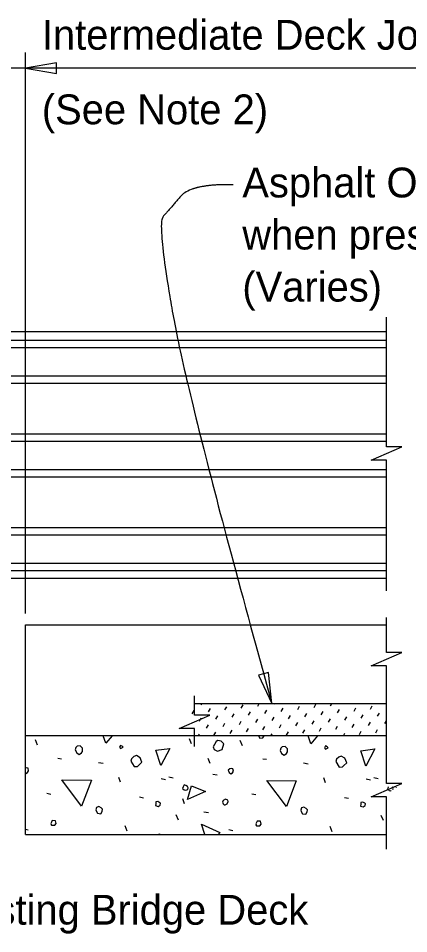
# Model space of a CAD drawing. Extents: x 21629.5 to 21698.8, y 56199.1 to 56237.6.
# Drawn here: x 21643.08 to 21645.71, y 56213.42 to 56219.6 of the extents above; entities that cross this region are included whole.
import ezdxf

# ---------------------------------------------------------------- set-up
doc = ezdxf.new("R2010")
doc.units = 0
for name, color, linetype in [('Dimension', 7, 'Continuous'), ('ExistSuperStruct', 7, 'Continuous'), ('Miscellaneous', 7, 'Continuous'), ('SteelMisc', 7, 'Continuous'), ('TextStructures', 7, 'Continuous')]:
    doc.layers.add(name, color=color, linetype=linetype)

msp = doc.modelspace()

# ---------------------------------------------------------------- linework, layer by layer
at = {"layer": 'Dimension'}
for p, q in [((21643.1252, 56215.5808), (21643.1252, 56219.372)), ((21647.048, 56219.267), (21641.4764, 56219.267))]:
    msp.add_line(p, q, dxfattribs=at)
for points in [[(21643.1251, 56219.267), (21643.3334, 56219.2318), (21643.3334, 56219.3023)], [(21644.7886, 56214.9723), (21644.7671, 56215.1824), (21644.6991, 56215.1636)]]:
    msp.add_lwpolyline(points, close=True, dxfattribs=at)
for points in [[(21645.5635, 56215.734), (21645.5635, 56216.6173), (21645.4601, 56216.6173), (21645.5635, 56216.6623), (21645.6668, 56216.7073), (21645.5635, 56216.7073), (21645.5635, 56217.5837)], [(21645.5635, 56214.7572), (21645.5635, 56215.2273), (21645.4601, 56215.2273), (21645.5635, 56215.2723), (21645.6668, 56215.3173), (21645.5635, 56215.3173), (21645.5635, 56215.5547)], [(21644.2668, 56214.6826), (21644.2668, 56214.8034), (21644.1635, 56214.8034), (21644.2668, 56214.8484), (21644.3701, 56214.8934), (21644.2668, 56214.8934), (21644.2668, 56215.024)], [(21645.5635, 56213.9879), (21645.5635, 56214.3427), (21645.4601, 56214.3427), (21645.5635, 56214.3877), (21645.6668, 56214.4327), (21645.5635, 56214.4327), (21645.5635, 56214.7572)]]:
    msp.add_lwpolyline(points, dxfattribs=at)
msp.add_open_spline([(21644.5276, 56218.4788), (21644.2443, 56218.4855), (21644.0959, 56218.3098), (21644.0132, 56218.2199), (21644.2161, 56217.0441), (21644.7886, 56214.9723)], degree=2, dxfattribs=at)
at = {"layer": 'ExistSuperStruct'}
for p, q in [((21643.1252, 56214.0879), (21643.1252, 56215.5045)), ((21643.1252, 56215.5045), (21645.5634, 56215.5045)), ((21644.2668, 56214.9734), (21645.5634, 56214.9734)), ((21645.5634, 56214.7545), (21643.1252, 56214.7545)), ((21643.1252, 56214.0879), (21645.5634, 56214.0879))]:
    msp.add_line(p, q, dxfattribs=at)
at = {"layer": 'Miscellaneous'}
for p, q in [((21644.2508, 56214.903), (21644.2638, 56214.9254)), ((21644.3126, 56214.9648), (21644.3176, 56214.9734)), ((21644.3615, 56214.916), (21644.3744, 56214.9384)), ((21644.4721, 56214.929), (21644.4851, 56214.9513)), ((21644.5827, 56214.9419), (21644.5957, 56214.9643)), ((21644.6316, 56214.8931), (21644.6445, 56214.9155)), ((21644.6934, 56214.9549), (21644.7041, 56214.9734)), ((21644.7422, 56214.906), (21644.7552, 56214.9284)), ((21644.804, 56214.9678), (21644.8072, 56214.9734)), ((21644.8528, 56214.919), (21644.8658, 56214.9414)), ((21644.9635, 56214.932), (21644.9764, 56214.9544)), ((21645.0741, 56214.9449), (21645.0871, 56214.9673)), ((21645.1229, 56214.8961), (21645.1359, 56214.9185)), ((21645.1847, 56214.9579), (21645.1937, 56214.9734)), ((21645.2336, 56214.9091), (21645.2465, 56214.9315)), ((21645.2954, 56214.9709), (21645.2969, 56214.9734)), ((21645.3442, 56214.922), (21645.3572, 56214.9444)), ((21645.4548, 56214.935), (21645.4678, 56214.9574)), ((21644.2997, 56214.8542), (21644.3126, 56214.8766)), ((21644.4103, 56214.8672), (21644.4233, 56214.8895)), ((21644.5209, 56214.8801), (21644.5339, 56214.9025)), ((21644.5698, 56214.8313), (21644.5827, 56214.8537)), ((21644.6804, 56214.8442), (21644.6934, 56214.8666)), ((21644.791, 56214.8572), (21644.804, 56214.8796)), ((21644.9017, 56214.8702), (21644.9146, 56214.8926)), ((21645.0123, 56214.8831), (21645.0253, 56214.9055)), ((21645.0611, 56214.8343), (21645.0741, 56214.8567)), ((21645.1718, 56214.8473), (21645.1847, 56214.8697)), ((21645.2824, 56214.8602), (21645.2954, 56214.8826)), ((21645.393, 56214.8732), (21645.406, 56214.8956)), ((21645.5037, 56214.8862), (21645.5166, 56214.9085)), ((21645.5525, 56214.8373), (21645.5634, 56214.8562)), ((21644.3485, 56214.8054), (21644.3615, 56214.8277)), ((21644.4591, 56214.8183), (21644.4721, 56214.8407)), ((21644.508, 56214.7695), (21644.5209, 56214.7919)), ((21644.6186, 56214.7824), (21644.6316, 56214.8048)), ((21644.7292, 56214.7954), (21644.7422, 56214.8178)), ((21644.8399, 56214.8084), (21644.8528, 56214.8308)), ((21644.9505, 56214.8213), (21644.9635, 56214.8437)), ((21644.9993, 56214.7725), (21645.0123, 56214.7949)), ((21645.11, 56214.7855), (21645.1229, 56214.8079)), ((21645.2206, 56214.7984), (21645.2336, 56214.8208)), ((21645.3312, 56214.8114), (21645.3442, 56214.8338)), ((21645.4419, 56214.8244), (21645.4548, 56214.8468)), ((21645.4907, 56214.7755), (21645.5037, 56214.7979)), ((21644.246, 56214.6996), (21644.2319, 56214.735)), ((21644.2931, 56214.7545), (21644.2997, 56214.766)), ((21644.3973, 56214.7565), (21644.4103, 56214.7789)), ((21644.6796, 56214.7545), (21644.6804, 56214.756)), ((21644.7827, 56214.7545), (21644.791, 56214.769)), ((21644.8887, 56214.7595), (21644.9017, 56214.7819)), ((21645.1692, 56214.7545), (21645.1718, 56214.759)), ((21645.2723, 56214.7545), (21645.2824, 56214.772)), ((21645.3801, 56214.7626), (21645.393, 56214.785)), ((21643.2054, 56214.6914), (21643.1913, 56214.7267)), ((21644.5901, 56214.6878), (21644.576, 56214.7232)), ((21643.3433, 56214.603), (21643.3681, 56214.5995)), ((21643.6191, 56214.5747), (21643.6492, 56214.5694)), ((21644.3715, 56214.567), (21644.3592, 56214.6006)), ((21644.728, 56214.5995), (21644.7528, 56214.5959)), ((21645.0038, 56214.5712), (21645.0338, 56214.5659)), ((21644.3904, 56214.4952), (21644.4204, 56214.4899)), ((21643.7676, 56214.4404), (21643.7552, 56214.4739)), ((21644.0416, 56214.4669), (21644.0699, 56214.4598)), ((21644.094, 56214.4769), (21644.1223, 56214.4698)), ((21645.1523, 56214.4368), (21645.1399, 56214.4704)), ((21645.4263, 56214.4633), (21645.4546, 56214.4563)), ((21645.4787, 56214.4733), (21645.507, 56214.4663)), ((21643.2691, 56214.3661), (21643.2956, 56214.3608)), ((21644.6538, 56214.3626), (21644.6803, 56214.3573)), ((21643.8949, 56214.3414), (21643.9214, 56214.3361)), ((21644.2001, 56214.2943), (21644.1877, 56214.3279)), ((21645.2796, 56214.3378), (21645.3061, 56214.3325)), ((21644.3303, 56214.2406), (21644.3621, 56214.2371)), ((21644.1576, 56214.1847), (21644.1435, 56214.22)), ((21645.5423, 56214.1811), (21645.5282, 56214.2165)), ((21643.1252, 56214.1228), (21643.1418, 56214.1186)), ((21643.8118, 56214.1098), (21643.7976, 56214.1451)), ((21644.4982, 56214.1222), (21644.5265, 56214.1151)), ((21645.1965, 56214.1063), (21645.1823, 56214.1416))]:
    msp.add_line(p, q, dxfattribs=at)
for points in [[(21643.6668, 56214.7038), (21643.6503, 56214.7545)], [(21643.7098, 56214.7545), (21643.6668, 56214.7038)], [(21644.7, 56214.7545), (21644.7086, 56214.7391), (21644.728, 56214.7409), (21644.7368, 56214.7533), (21644.737, 56214.7545)], [(21645.0515, 56214.7002), (21645.0338, 56214.7545)], [(21645.0975, 56214.7545), (21645.0515, 56214.7002)], [(21643.46, 56214.6596), (21643.4706, 56214.6384), (21643.4883, 56214.6277), (21643.5024, 56214.6384), (21643.5095, 56214.649), (21643.5095, 56214.6702), (21643.4936, 56214.6861), (21643.4741, 56214.6843), (21643.4653, 56214.6755), (21643.46, 56214.6596)], [(21643.7658, 56214.6684), (21643.7853, 56214.6772), (21643.7782, 56214.6843), (21643.7658, 56214.6896), (21643.7605, 56214.6772), (21643.7658, 56214.6684)], [(21644.0392, 56214.5529), (21644.0056, 56214.6572), (21644.0993, 56214.6695), (21644.0392, 56214.5529)], [(21644.3998, 56214.6625), (21644.4228, 56214.6501), (21644.4529, 56214.6625), (21644.4652, 56214.6996), (21644.4476, 56214.7173), (21644.4246, 56214.7226), (21644.414, 56214.7155), (21644.4016, 56214.6961), (21644.3928, 56214.6802), (21644.3998, 56214.6625)], [(21644.8447, 56214.656), (21644.8553, 56214.6348), (21644.873, 56214.6242), (21644.8871, 56214.6348), (21644.8942, 56214.6454), (21644.8942, 56214.6666), (21644.8783, 56214.6825), (21644.8588, 56214.6808), (21644.85, 56214.6719), (21644.8447, 56214.656)], [(21645.1505, 56214.6649), (21645.17, 56214.6737), (21645.1629, 56214.6808), (21645.1505, 56214.6861), (21645.1452, 56214.6737), (21645.1505, 56214.6649)], [(21643.8365, 56214.5836), (21643.8595, 56214.5464), (21643.8825, 56214.5482), (21643.8913, 56214.557), (21643.9108, 56214.5765), (21643.8984, 56214.6065), (21643.8737, 56214.6207), (21643.856, 56214.6136), (21643.8418, 56214.5995), (21643.8365, 56214.5836)], [(21645.2212, 56214.58), (21645.2442, 56214.5429), (21645.2672, 56214.5447), (21645.276, 56214.5535), (21645.2955, 56214.5729), (21645.2831, 56214.603), (21645.2583, 56214.6171), (21645.2407, 56214.6101), (21645.2265, 56214.5959), (21645.2212, 56214.58)], [(21645.4239, 56214.5493), (21645.3903, 56214.6536), (21645.484, 56214.666), (21645.4239, 56214.5493)], [(21643.1252, 56214.5029), (21643.1277, 56214.5005), (21643.1383, 56214.5075), (21643.1453, 56214.5181), (21643.1418, 56214.5358), (21643.133, 56214.5376), (21643.1252, 56214.5365)], [(21644.5017, 56214.5075), (21644.5123, 56214.4969), (21644.5229, 56214.504), (21644.53, 56214.5146), (21644.5265, 56214.5323), (21644.5176, 56214.5341), (21644.5053, 56214.5323), (21644.4947, 56214.5217), (21644.5017, 56214.5075)], [(21643.5042, 56214.2795), (21643.3698, 56214.4563), (21643.5696, 56214.4545), (21643.5042, 56214.2795)], [(21644.1965, 56214.3885), (21644.2089, 56214.3867), (21644.2213, 56214.392), (21644.2248, 56214.4026), (21644.2195, 56214.4115), (21644.2089, 56214.4185), (21644.1965, 56214.4238), (21644.1895, 56214.4097), (21644.1859, 56214.3991), (21644.1965, 56214.3885)], [(21644.8889, 56214.276), (21644.7545, 56214.4527), (21644.9543, 56214.451), (21644.8889, 56214.276)], [(21644.2189, 56214.3237), (21644.2472, 56214.4156), (21644.3409, 56214.3785), (21644.2189, 56214.3237)], [(21645.5756, 56214.409), (21645.5741, 56214.4061), (21645.5706, 56214.3955), (21645.5812, 56214.3849)], [(21645.5812, 56214.3849), (21645.5936, 56214.3832), (21645.5955, 56214.384)], [(21645.6068, 56214.391), (21645.6095, 56214.3991), (21645.6042, 56214.4079), (21645.6026, 56214.409)], [(21645.6297, 56214.4051), (21645.6309, 56214.409)], [(21644.0027, 56214.283), (21644.0222, 56214.2777), (21644.0345, 56214.2866), (21644.0363, 56214.2989), (21644.0328, 56214.3025), (21644.0186, 56214.3095), (21644.0062, 56214.3078), (21644.0045, 56214.2954), (21644.0027, 56214.283)], [(21644.4664, 56214.2883), (21644.4735, 56214.2883), (21644.4876, 56214.2954), (21644.4929, 56214.3113), (21644.4911, 56214.3202), (21644.477, 56214.3272), (21644.4593, 56214.3166), (21644.4558, 56214.306), (21644.4593, 56214.2954), (21644.4664, 56214.2883)], [(21645.3874, 56214.2795), (21645.4068, 56214.2742), (21645.4192, 56214.283), (21645.421, 56214.2954), (21645.4174, 56214.2989), (21645.4033, 56214.306), (21645.3909, 56214.3042), (21645.3892, 56214.2919), (21645.3874, 56214.2795)], [(21643.6032, 56214.2477), (21643.612, 56214.2318), (21643.6332, 56214.2282), (21643.6421, 56214.2441), (21643.6456, 56214.2583), (21643.6368, 56214.2671), (21643.6209, 56214.276), (21643.605, 56214.2707), (21643.5997, 56214.2547), (21643.6032, 56214.2477)], [(21644.9879, 56214.2441), (21644.9967, 56214.2282), (21645.0179, 56214.2247), (21645.0268, 56214.2406), (21645.0303, 56214.2547), (21645.0215, 56214.2636), (21645.0055, 56214.2724), (21644.9896, 56214.2671), (21644.9843, 56214.2512), (21644.9879, 56214.2441)], [(21643.3009, 56214.1504), (21643.3221, 56214.1504), (21643.3327, 56214.1611), (21643.3274, 56214.1805), (21643.3044, 56214.1823), (21643.3009, 56214.1717), (21643.2956, 56214.1628), (21643.3009, 56214.1504), (21643.2974, 56214.154)], [(21644.6856, 56214.1469), (21644.7068, 56214.1469), (21644.7174, 56214.1575), (21644.7121, 56214.177), (21644.6891, 56214.1787), (21644.6856, 56214.1681), (21644.6803, 56214.1593), (21644.6856, 56214.1469), (21644.682, 56214.1504)], [(21644.3355, 56214.0879), (21644.3132, 56214.1564), (21644.4387, 56214.1016), (21644.4271, 56214.0879)], [(21644.0335, 56214.0879), (21644.0268, 56214.0892), (21644.0228, 56214.0879)]]:
    msp.add_lwpolyline(points, dxfattribs=at)
at = {"layer": 'SteelMisc'}
for p, q in [((21645.5634, 56217.4837), (21637.423, 56217.4837)), ((21637.423, 56217.4282), (21645.5634, 56217.4282)), ((21637.423, 56217.38), (21645.5634, 56217.38)), ((21637.423, 56217.1871), (21645.5634, 56217.1871)), ((21637.423, 56217.1389), (21645.5634, 56217.1389)), ((21637.423, 56216.795), (21645.5634, 56216.795)), ((21637.423, 56216.7467), (21645.5634, 56216.7467)), ((21637.423, 56216.5539), (21645.5634, 56216.5539)), ((21637.423, 56216.5058), (21645.5634, 56216.5058)), ((21637.423, 56216.1618), (21645.5634, 56216.1618)), ((21637.423, 56216.1136), (21645.5634, 56216.1136)), ((21637.423, 56215.9208), (21645.5634, 56215.9208)), ((21637.423, 56215.8726), (21645.5634, 56215.8726)), ((21645.5634, 56215.817), (21637.423, 56215.817))]:
    msp.add_line(p, q, dxfattribs=at)

# ---------------------------------------------------------------- texts
at = {"layer": 'Dimension'}
for s, p in [('Asphalt Overlay', (21644.5895, 56218.3932)), ('when present', (21644.5895, 56218.0412)), ('(Varies)', (21644.5895, 56217.6892))]:
    msp.add_text(s, height=0.2016, dxfattribs=at).set_placement(p)
at = {"layer": 'TextStructures'}
for s, p in [('Intermediate Deck Joint', (21643.2352, 56219.3914)), ('(See Note 2)', (21643.2352, 56218.8874)), ('Existing Bridge Deck', (21642.5478, 56213.478))]:
    msp.add_text(s, height=0.2016, dxfattribs=at).set_placement(p)

doc.saveas('drawing.dxf')
